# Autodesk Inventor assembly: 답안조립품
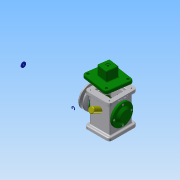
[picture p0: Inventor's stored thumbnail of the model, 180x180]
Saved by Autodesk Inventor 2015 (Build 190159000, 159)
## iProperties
Created: 2017-08
Part Number: 답안조립품
Document SubType Name: Weldment
Designer: Administrator
Weld Material: Welded Aluminum-6061
Author: Administrator
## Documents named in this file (18)
- C:\Users\Administrator\Desktop\470807V1009\답안조립품.iam
- C:\Users\Administrator\Desktop\470807V1009\본체.ipt
- C:\Users\Administrator\Desktop\470807V1009\E-링.ipt
- C:\Users\Administrator\Desktop\470807V1009\V-벨트풀리.ipt
- C:\Users\Administrator\Desktop\470807V1009\덮개.ipt
- C:\Users\Administrator\Desktop\470807V1009\뒤커버.ipt
- C:\Users\Administrator\Desktop\470807V1009\링크.ipt
- C:\Users\Administrator\Desktop\470807V1009\베어링 17 x 40 x 12.ipt
- C:\Users\Administrator\Desktop\470807V1009\볼트 M4 x 8.ipt
- C:\Users\Administrator\Desktop\470807V1009\볼트 M4 x 10.ipt
- C:\Users\Administrator\Desktop\470807V1009\슬라이더.ipt
- C:\Users\Administrator\Desktop\470807V1009\앞커버.ipt
- C:\Users\Administrator\Desktop\470807V1009\오일 실 17 30 8.ipt
- C:\Users\Administrator\Desktop\470807V1009\와셔 4x16.ipt
- C:\Users\Administrator\Desktop\470807V1009\클레비스 핀 6 x 22.ipt
- 클레비스 핀 6 x 22.ipt
- C:\Users\Administrator\Desktop\470807V1009\키 4 x 4 x 12.ipt
- C:\Users\Administrator\Desktop\470807V1009\편심축.ipt
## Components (2 placed, 2 different names)
1. E-링:1
2. V-벨트풀리:1 — 각도:1
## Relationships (1: Angle 1)
- 각도:1 [Angle]: V-벨트풀리:1
